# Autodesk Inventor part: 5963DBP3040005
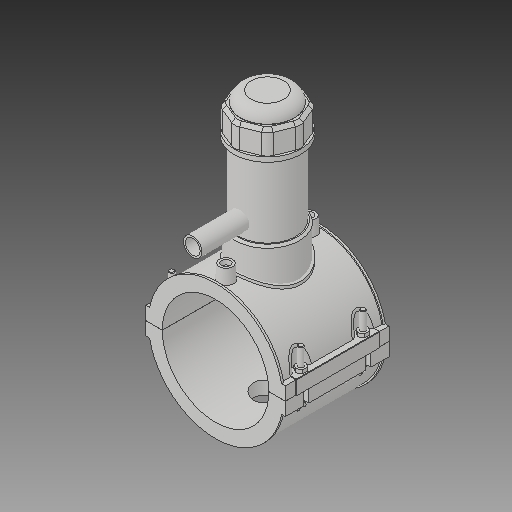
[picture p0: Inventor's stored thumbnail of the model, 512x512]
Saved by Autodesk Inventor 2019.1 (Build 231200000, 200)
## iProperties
Created: 2017-07
Part Number: 5963DBP3040005
Material: Generic
Description: PLASSON TAPPING SADDLE 4''DIPS x 1/2''IPS
Document SubType Name: Modeling
Designer: KIM
Density: 1 g/cm^3
Appearance: Default
Author: KIM
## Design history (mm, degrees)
derived "5963DBP_5963BUP.ipt"
feature "Solid1::5963DBP_5963BUP.ipt"
feature "Solid2::5963DBP_5963BUP.ipt"
feature "Solid3::5963DBP_5963BUP.ipt"
tag "TaggingFeature1"
body "Solid1"
body "Solid2"
body "Solid3"
other parameters: "d0" = 121.3, "d2" = 159.004, "d3" = 30.325, "d4" = 118.11, "d5" = 0, "d6" = 0.1, "d8" = 0, "d19" = 6, "d20" = 6, "d21" = 70.866, "d23" = 0, "d24" = 35.433, "d26" = 0, "d27" = 3, "d28" = 3, "d29" = 3, "d30" = 40.43333, "d31" = 6, "d32" = 0, "d33" = 0, "d34" = 0.6, "d40" = 78.21424, "d41" = 76.419, "d43" = 0, "d45" = 0, "d47" = 146.072, "d70" = 15, "d72" = 0, "d73" = 6, "d75" = 5, "d76" = 0, "d77" = 6.065, "d78" = 90.65, "d79" = 15, "d80" = 47.244, "d82" = 5 deg, "d84" = 4, "d85" = 14, "d86" = 0, "d87" = 3, "d88" = 0, "d89" = 1, "d90" = 1, "d91" = 94.488, "d92" = 0, "d93" = 0.5, "d94" = 63.84211, "d96" = 153.42024, "d97" = 2.3622, "d98" = 0, "d120" = 140 deg, "d121" = 24.228, "d122" = 20 deg, "d123" = 300.824, "d124" = 90.2472, "d126" = 0, "d143" = 124.939, "d145" = 22.39385, "d149" = 1.8195, "d150" = 24.63323, "d153" = 118.11, "d154" = 0, "d156" = 75.206, "d157" = 160 deg, "d159" = 5.8224, "d161" = 1.8195, "d162" = 70.866, "d163" = 0, "d164" = 60.65, "d167" = 12.13, "d168" = 73.37171, "d170" = 3.4335, "d172" = 0, "d173" = 1, "d175" = 60.65, "d176" = 20 deg, "d177" = 8.491, "d178" = 29.112, "d180" = 0, "d183" = 11.6448, "d184" = 6.7928, "d185" = 38.38575, "d186" = 38.38575, "d187" = 75.206, "d188" = 8.7336, "d189" = 8.491, "d190" = 0, "d191" = 112.809, "d193" = 7.3248, "d194" = 4.13385, "d195" = 90 deg, "d197" = 0, "d199" = 0, "d200" = 14.556, "d202" = 0, "d203" = 177.038, "d204" = 72.59805, "d205" = 53.4933, "d206" = 64.95615, "d207" = 132.7785, "d208" = 138.08964, "d209" = 164.64534, "d210" = 65.72034, "d211" = 76.419, "d212" = 61.1352, "d213" = 48.9816, "d216" = 0, "d217" = 12.13, "d218" = 12.13, "d219" = 2.426, "d222" = 121.3, "d224" = 0, "d225" = 65.024, "d226" = 21.2, "d227" = 16.96, "d228" = 85.09, "d230" = 3.639, "d_" = 121.3, "B_" = 159.004, "L_" = 118.11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
